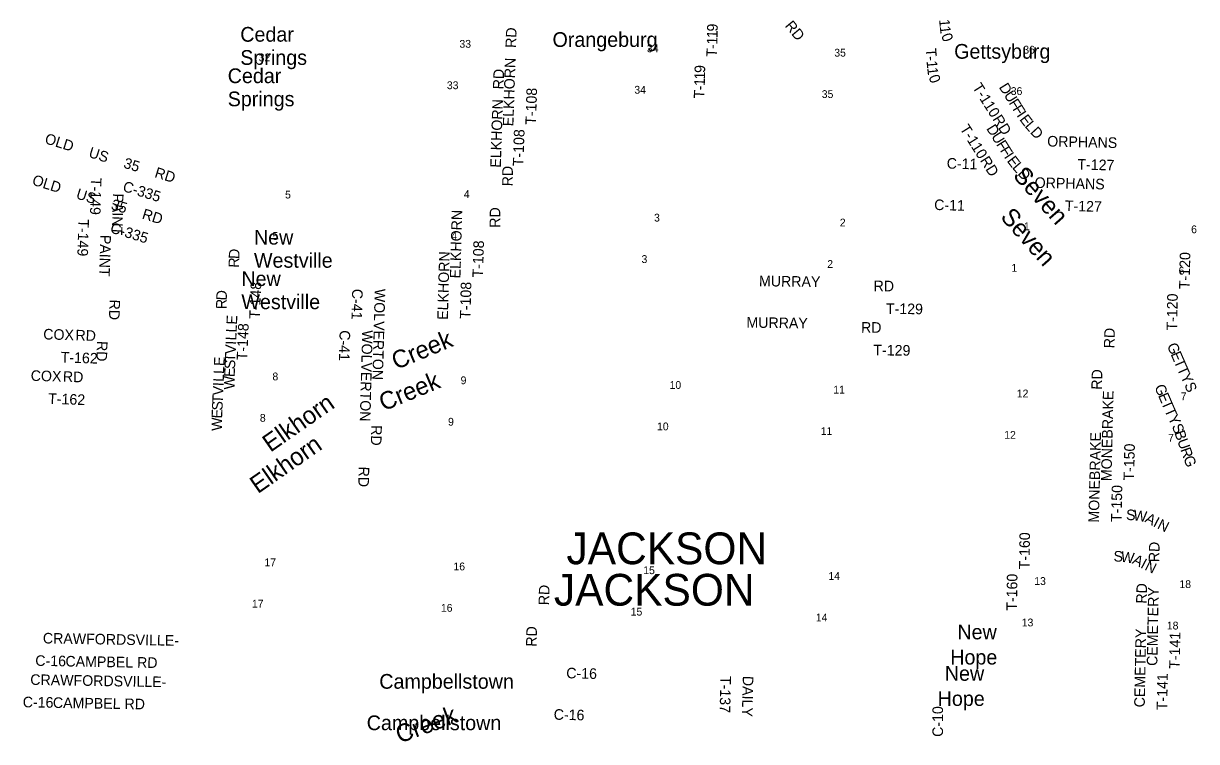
# Model space of a CAD drawing. Extents: x -21.9 to 47.3, y 14.1 to 48.7.
# Drawn here: x -21.95 to -15.65, y 40.85 to 44.7 of the extents above; entities that cross this region are included whole.
import ezdxf

# ---------------------------------------------------------------- set-up
doc = ezdxf.new("R2010")
doc.units = 0
for name, color, linetype in [('GM_X_County_Road_Text', 7, 'Continuous'), ('GM_X_Major_River_Text', 7, 'Continuous'), ('GM_X_Minor_River_Text', 7, 'Continuous'), ('GM_X_Section_Text', 7, 'Continuous'), ('GM_X_Township_Road_Text', 7, 'Continuous'), ('GM_X_Township_Text', 7, 'Continuous'), ('GM_X_Unincorporated_Text', 7, 'Continuous')]:
    doc.layers.add(name, color=color, linetype=linetype)

msp = doc.modelspace()

# ---------------------------------------------------------------- texts
at = {"layer": 'GM_X_County_Road_Text'}
for s, height, rotation, p in [('RD', 0.05682, 309.74193, (-17.8643, 44.6863)), ('OLD', 0.05682, 342.62515, (-21.8365, 44.0589)), ('US', 0.05682, 342.74028, (-21.6008, 43.9847)), ('35', 0.05682, 343.30189, (-21.4135, 43.9273)), ('C-11', 0.05682, 358.2847, (-16.9937, 43.9222)), ('OLD', 0.05682, 342.62515, (-21.9039, 43.8367)), ('RD', 0.05682, 342.96967, (-21.2467, 43.8764)), ('US', 0.05682, 342.74028, (-21.6681, 43.7626)), ('C-335', 0.05682, 342.95879, (-21.418, 43.8023)), ('35', 0.05682, 343.30189, (-21.4809, 43.7051)), ('C-11', 0.05682, 358.2847, (-17.0611, 43.7)), ('RD', 0.05682, 342.96967, (-21.3141, 43.6542)), ('C-335', 0.05682, 342.95879, (-21.4854, 43.5801)), ('C-41', 0.05682, 268.62783, (-20.1828, 43.2774)), ('WOLVERTON', 0.05682, 268.48115, (-20.0617, 43.2778)), ('C-41', 0.05682, 268.62783, (-20.2501, 43.0552)), ('WOLVERTON', 0.05682, 268.48115, (-20.1291, 43.0556)), ('G', 0.0568, 293.23244, (-15.8123, 42.9728)), ('E', 0.0568, 293.24953, (-15.7926, 42.9268)), ('T', 0.0568, 293.34857, (-15.7757, 42.8877)), ('T', 0.0568, 293.75813, (-15.7587, 42.8482)), ('Y', 0.0568, 296.16234, (-15.7405, 42.807)), ('G', 0.0568, 293.23244, (-15.8797, 42.7506)), ('S', 0.0568, 291.28348, (-15.719, 42.7633)), ('E', 0.0568, 293.24953, (-15.8599, 42.7046)), ('T', 0.0568, 293.34857, (-15.8431, 42.6655)), ('T', 0.0568, 293.75813, (-15.8261, 42.626)), ('Y', 0.0568, 296.16234, (-15.8079, 42.5848)), ('S', 0.0568, 291.28348, (-15.7864, 42.5411)), ('RD', 0.05682, 268.51865, (-20.0801, 42.5461)), ('B', 0.0568, 289.55197, (-15.7726, 42.5058)), ('U', 0.0568, 289.28885, (-15.757, 42.4619)), ('R', 0.0568, 289.36822, (-15.7405, 42.4146)), ('G', 0.0568, 290.55412, (-15.7245, 42.3694)), ('RD', 0.05682, 268.51865, (-20.1475, 42.3239)), ('RD', 0.05682, 88.51842, (-19.1264, 41.579)), ('CRAWFORDSVILLE-', 0.056818, 358.98087, (-21.8428, 41.3749)), ('RD', 0.05682, 88.51842, (-19.1938, 41.3568)), ('C-16', 0.05682, 358.9701, (-21.8833, 41.2547)), ('CAMPBEL RD', 0.05682, 359.02727, (-21.7216, 41.2513)), ('C-16', 0.05682, 358.62866, (-19.0348, 41.188)), ('CRAWFORDSVILLE-', 0.056818, 358.98087, (-21.9102, 41.1527)), ('C-16', 0.05682, 358.9701, (-21.9507, 41.0325)), ('CAMPBEL RD', 0.05682, 359.02727, (-21.789, 41.0292)), ('C-16', 0.05682, 358.62866, (-19.1021, 40.9658)), ('C-10', 0.05682, 90, (-17.0129, 40.8734))]:
    msp.add_text(s, height=height, rotation=rotation, dxfattribs=at).set_placement(p)
at = {"layer": 'GM_X_Major_River_Text'}
for s, height, rotation, p in [('Seven', 0.09475, 311.42284, (-16.642, 43.8817)), ('Seven', 0.09475, 311.42284, (-16.7094, 43.6595)), ('Creek', 0.09469, 20.2646, (-19.9285, 40.8374))]:
    msp.add_text(s, height=height, rotation=rotation, dxfattribs=at).set_placement(p)
at = {"layer": 'GM_X_Minor_River_Text'}
for s, rotation, p in [('Creek', 22.51609, (-19.9472, 42.8415)), ('Creek', 22.51609, (-20.0146, 42.6193)), ('Elkhorn', 34.92757, (-20.6216, 42.3974)), ('Elkhorn', 34.92757, (-20.689, 42.1752))]:
    msp.add_text(s, height=0.09474, rotation=rotation, dxfattribs=at).set_placement(p)
at = {"layer": 'GM_X_Section_Text'}
for s, height, p in [('33', 0.04186, (-19.6074, 44.5701)), ('34', 0.04186, (-18.6016, 44.5459)), ('35', 0.04186, (-17.5962, 44.5226)), ('36', 0.04186, (-16.582, 44.5388)), ('32', 0.04186, (-20.6844, 44.4971)), ('33', 0.04186, (-19.6748, 44.3479)), ('34', 0.04186, (-18.669, 44.3237)), ('35', 0.04186, (-17.6635, 44.3004)), ('36', 0.04186, (-16.6494, 44.3167)), ('4', 0.0419, (-19.5836, 43.7642)), ('5', 0.0419, (-20.5428, 43.7615)), ('3', 0.0419, (-18.5632, 43.6376)), ('2', 0.0419, (-17.5666, 43.6112)), ('1', 0.0419, (-16.5787, 43.5909)), ('6', 0.0419, (-15.6816, 43.5751)), ('5', 0.0419, (-20.6102, 43.5393)), ('4', 0.0419, (-19.651, 43.542)), ('3', 0.0419, (-18.6306, 43.4154)), ('2', 0.0419, (-17.634, 43.3891)), ('1', 0.0419, (-16.646, 43.3687)), ('6', 0.0419, (-15.749, 43.3529)), ('8', 0.0419, (-20.6107, 42.7859)), ('9', 0.0419, (-19.6011, 42.7651)), ('10', 0.04186, (-18.4799, 42.7401)), ('11', 0.04186, (-17.6016, 42.7151)), ('12', 0.04186, (-16.617, 42.6946)), ('7', 0.0419, (-15.7378, 42.679)), ('8', 0.0419, (-20.6781, 42.5638)), ('9', 0.0419, (-19.6685, 42.5429)), ('10', 0.04186, (-18.5473, 42.5179)), ('11', 0.04186, (-17.669, 42.4929)), ('12', 0.04186, (-16.6844, 42.4724)), ('7', 0.0419, (-15.8052, 42.4568)), ('17', 0.04186, (-20.6536, 41.789)), ('16', 0.04186, (-19.6395, 41.7668)), ('15', 0.04186, (-18.6211, 41.7465)), ('14', 0.04186, (-17.6278, 41.7154)), ('13', 0.04186, (-16.5232, 41.6884)), ('18', 0.04186, (-15.7445, 41.6718)), ('17', 0.04186, (-20.721, 41.5668)), ('16', 0.04186, (-19.7069, 41.5446)), ('15', 0.04186, (-18.6885, 41.5243)), ('14', 0.04186, (-17.6952, 41.4932)), ('13', 0.04186, (-16.5906, 41.4662)), ('18', 0.04186, (-15.8119, 41.4496))]:
    msp.add_text(s, height=height, rotation=0.00001, dxfattribs=at).set_placement(p)
at = {"layer": 'GM_X_Township_Road_Text'}
for s, height, rotation, p in [('9', 0.0568, 88.72552, (-18.2222, 44.6564)), ('1', 0.0568, 274.89319, (-17.034, 44.7213)), ('RD', 0.05682, 88.02499, (-19.3039, 44.5683)), ('1', 0.0568, 88.61137, (-18.2238, 44.5863)), ('1', 0.0568, 88.70631, (-18.2229, 44.6214)), ('1', 0.0568, 276.75399, (-17.0308, 44.6845)), ('0', 0.0568, 289.44852, (-17.0236, 44.6364)), ('T', 0.0568, 87.19868, (-18.2266, 44.519)), ('-', 0.0568, 88.37721, (-18.2245, 44.5628)), ('T', 0.0568, 274.3476, (-17.1065, 44.5654)), ('ELKHORN', 0.05682, 88.1291, (-19.3181, 44.1481)), ('-', 0.0568, 274.45309, (-17.1032, 44.5229)), ('RD', 0.05682, 88.02499, (-19.3713, 44.3461)), ('9', 0.0568, 88.72552, (-18.2895, 44.4342)), ('1', 0.0568, 88.70631, (-18.2903, 44.3992)), ('1', 0.0568, 274.89319, (-17.1014, 44.4992)), ('1', 0.0568, 276.75399, (-17.0982, 44.4623)), ('1', 0.0568, 88.61137, (-18.2912, 44.3641)), ('0', 0.0568, 289.44852, (-17.091, 44.4142)), ('T-110', 0.05682, 302.2133, (-16.8575, 44.3583)), ('D', 0.0568, 302.04879, (-16.715, 44.3587)), ('T-108', 0.05682, 88.03459, (-19.1972, 44.1558)), ('T', 0.0568, 87.19868, (-18.294, 44.2968)), ('-', 0.0568, 88.37721, (-18.2919, 44.3406)), ('U', 0.0568, 302.04879, (-16.6885, 44.3164)), ('ELKHORN', 0.05682, 88.1291, (-19.3855, 43.926)), ('F', 0.0568, 302.04879, (-16.6619, 44.274)), ('F', 0.0568, 302.04879, (-16.6416, 44.2415)), ('RD', 0.05682, 302.31985, (-16.7491, 44.1878)), ('I', 0.0568, 303.78841, (-16.6203, 44.2074)), ('E', 0.0568, 307.26764, (-16.6051, 44.185)), ('T-108', 0.05682, 88.03459, (-19.2646, 43.9336)), ('T-110', 0.05682, 302.2133, (-16.9249, 44.1361)), ('D', 0.0568, 302.04879, (-16.7824, 44.1365)), ('L', 0.0568, 310.74687, (-16.5771, 44.1483)), ('D', 0.0568, 312.48649, (-16.5481, 44.1147)), ('U', 0.0568, 302.04879, (-16.7559, 44.0942)), ('F', 0.0568, 302.04879, (-16.7293, 44.0518)), ('ORPHANS', 0.05682, 358.67479, (-16.4544, 44.0407)), ('F', 0.0568, 302.04879, (-16.709, 44.0193)), ('I', 0.0568, 303.78841, (-16.6876, 43.9852)), ('RD', 0.05682, 89.51517, (-19.3214, 43.8266)), ('RD', 0.05682, 302.31985, (-16.8165, 43.9656)), ('E', 0.0568, 307.26764, (-16.6725, 43.9628)), ('L', 0.0568, 310.74687, (-16.6444, 43.9261)), ('T-127', 0.05682, 358.59568, (-16.2923, 43.9165)), ('T-149', 0.05682, 268.31531, (-21.5843, 43.8729)), ('D', 0.0568, 312.48649, (-16.6155, 43.8926)), ('ORPHANS', 0.05682, 358.67479, (-16.5218, 43.8185)), ('PAINT', 0.05682, 268.12979, (-21.4661, 43.7893)), ('T-127', 0.05682, 358.59568, (-16.3597, 43.6943)), ('ELKHORN', 0.05682, 88.42091, (-19.6022, 43.3323)), ('RD', 0.05682, 89.51517, (-19.3888, 43.6044)), ('T-149', 0.05682, 268.31531, (-21.6517, 43.6508)), ('PAINT', 0.05682, 268.12979, (-21.5335, 43.5671)), ('T-108', 0.05682, 88.31531, (-19.4813, 43.3371)), ('R', 0.0568, 88.6192, (-20.7897, 43.3897)), ('D', 0.0568, 87.72195, (-20.7886, 43.4361)), ('ELKHORN', 0.05682, 88.42091, (-19.6696, 43.1101)), ('T-120', 0.05682, 88.87678, (-15.6896, 43.2748)), ('T-148', 0.05682, 87.49869, (-20.6789, 43.1148)), ('T-108', 0.05682, 88.31531, (-19.5487, 43.115)), ('MURRAY', 0.05682, 359.21715, (-18.0004, 43.2908)), ('RD', 0.05682, 359.50635, (-17.3855, 43.2641)), ('D', 0.0568, 87.72195, (-20.856, 43.2139)), ('T-120', 0.05682, 88.87678, (-15.757, 43.0526)), ('RD', 0.05682, 268.0251, (-21.4844, 43.2201)), ('R', 0.0568, 88.6192, (-20.8571, 43.1675)), ('T-129', 0.05682, 359.4386, (-17.3192, 43.1423)), ('E', 0.0568, 87.42776, (-20.801, 43.0841)), ('MURRAY', 0.05682, 359.21715, (-18.0678, 43.0686)), ('COX', 0.05682, 358.37237, (-21.8409, 43.0057)), ('RD', 0.05682, 358.02427, (-21.6683, 43.0007)), ('L', 0.0568, 87.42725, (-20.8029, 43.0417)), ('T-148', 0.05682, 87.49869, (-20.7463, 42.8926)), ('RD', 0.05682, 359.50635, (-17.4529, 43.0419)), ('RD', 0.05682, 88.51842, (-16.0931, 42.9573)), ('RD', 0.05682, 268.0251, (-21.5518, 42.9979)), ('I', 0.0568, 87.42552, (-20.8058, 42.9759)), ('L', 0.0568, 87.42776, (-20.8048, 42.9992)), ('T-162', 0.05682, 358.03475, (-21.7474, 42.8823)), ('T', 0.0568, 87.42776, (-20.81, 42.8835)), ('V', 0.0568, 87.42737, (-20.8081, 42.926)), ('T-129', 0.05682, 359.4386, (-17.3866, 42.9201)), ('E', 0.0568, 87.42776, (-20.8684, 42.8619)), ('S', 0.0568, 87.42732, (-20.8117, 42.8452)), ('COX', 0.05682, 358.37237, (-21.9083, 42.7835)), ('RD', 0.05682, 358.02427, (-21.7357, 42.7785)), ('L', 0.0568, 87.42776, (-20.8722, 42.777)), ('L', 0.0568, 87.42725, (-20.8703, 42.8195)), ('W', 0.0568, 90.35743, (-20.8131, 42.7377)), ('E', 0.0568, 87.60691, (-20.8135, 42.8028)), ('RD', 0.05682, 88.51842, (-16.1605, 42.7351)), ('V', 0.0568, 87.42737, (-20.8755, 42.7038)), ('I', 0.0568, 87.42552, (-20.8732, 42.7537)), ('T-162', 0.05682, 358.03475, (-21.8148, 42.6601)), ('T', 0.0568, 87.42776, (-20.8774, 42.6613)), ('MONEBRAKE', 0.05682, 88.70049, (-16.1089, 42.2447)), ('E', 0.0568, 87.60691, (-20.8809, 42.5806)), ('S', 0.0568, 87.42732, (-20.8791, 42.623)), ('W', 0.0568, 90.35743, (-20.8804, 42.5155)), ('MONEBRAKE', 0.05682, 88.70049, (-16.1763, 42.0225)), ('T-150', 0.05682, 88.59592, (-15.988, 42.2476)), ('T-150', 0.05682, 88.59592, (-16.0554, 42.0254)), ('S', 0.0568, 358.70274, (-16.0311, 42.0366)), ('W', 0.0568, 352.01447, (-15.9945, 42.0358)), ('A', 0.0568, 332.69615, (-15.9341, 42.0282)), ('I', 0.0568, 332.16675, (-15.8898, 42.0053)), ('N', 0.0568, 334.26263, (-15.8671, 41.9934)), ('T-160', 0.05682, 89.1574, (-16.5488, 41.7719)), ('S', 0.0568, 358.70274, (-16.0985, 41.8144)), ('W', 0.0568, 352.01447, (-16.0619, 41.8136)), ('RD', 0.05682, 88.51884, (-15.8531, 41.8098)), ('A', 0.0568, 332.69615, (-16.0015, 41.806)), ('I', 0.0568, 332.16675, (-15.9572, 41.7832)), ('N', 0.0568, 334.26263, (-15.9345, 41.7712)), ('T-160', 0.05682, 89.1574, (-16.6162, 41.5497)), ('RD', 0.05682, 88.51884, (-15.9205, 41.5876)), ('CEMETERY', 0.05682, 88.97931, (-15.8631, 41.2538)), ('CEMETERY', 0.05682, 88.97931, (-15.9305, 41.0316)), ('T-141', 0.05682, 88.87652, (-15.743, 41.2381)), ('T-137', 0.05682, 268.59592, (-18.2068, 41.2008)), ('DAILY', 0.05682, 268.45186, (-18.0866, 41.2011)), ('T-141', 0.05682, 88.87652, (-15.8104, 41.0159))]:
    msp.add_text(s, height=height, rotation=rotation, dxfattribs=at).set_placement(p)
at = {"layer": 'GM_X_Township_Text'}
for p in [(-19.0331, 41.7996), (-19.1005, 41.5774)]:
    msp.add_text('JACKSON', height=0.17045, rotation=0.00001, dxfattribs=at).set_placement(p)
at = {"layer": 'GM_X_Unincorporated_Text'}
for s, height, p in [('Cedar', 0.07898, (-20.7832, 44.6025)), ('Orangeburg', 0.07898, (-19.1081, 44.5745)), ('Springs', 0.07898, (-20.7832, 44.4783)), ('Gettsyburg', 0.07898, (-16.9531, 44.5111)), ('Cedar', 0.07898, (-20.8506, 44.3803)), ('Springs', 0.07898, (-20.8506, 44.2561)), ('New', 0.07898, (-20.7099, 43.5142)), ('Westville', 0.07898, (-20.7099, 43.39)), ('New', 0.07898, (-20.7773, 43.292)), ('Westville', 0.07898, (-20.7773, 43.1678)), ('New', 0.07898, (-16.9357, 41.3967)), ('Hope', 0.07898, (-16.9741, 41.2617)), ('New', 0.07898, (-17.0031, 41.1745)), ('Campbellstown', 0.078977, (-20.0374, 41.1317)), ('Hope', 0.07898, (-17.0415, 41.0395)), ('Campbellstown', 0.078977, (-20.1048, 40.9095))]:
    msp.add_text(s, height=height, rotation=0.00001, dxfattribs=at).set_placement(p)

doc.saveas('drawing.dxf')
